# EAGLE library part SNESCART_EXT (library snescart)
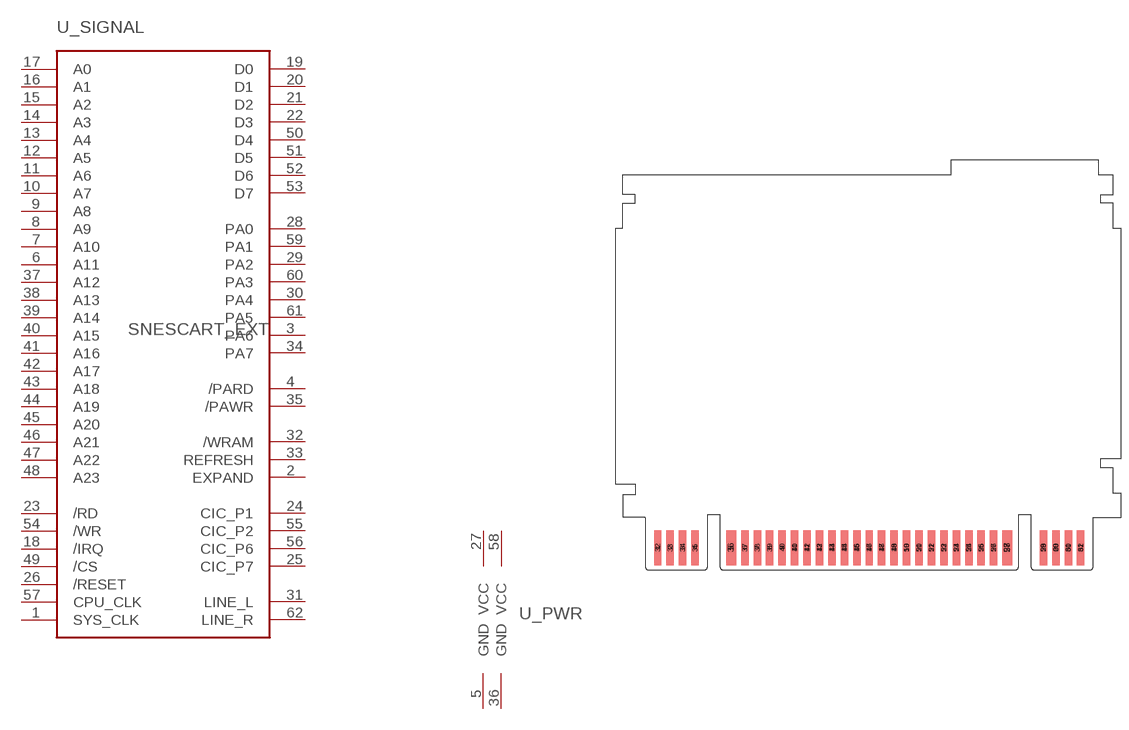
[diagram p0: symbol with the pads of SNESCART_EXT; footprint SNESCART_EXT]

Designator prefix -; gates _PWR=CART_PWR _SIGNAL=SNESCART_EXT

## SNESCART_EXTEDGE  [SNESCART_EXT]
1  _SIGNAL:SYS_CLK
2  _SIGNAL:EXPAND
3  _SIGNAL:PA6
4  _SIGNAL:/PARD
5  _PWR:GND  pwr
6  _SIGNAL:A11
7  _SIGNAL:A10
8  _SIGNAL:A9
9  _SIGNAL:A8
10  _SIGNAL:A7
11  _SIGNAL:A6
12  _SIGNAL:A5
13  _SIGNAL:A4
14  _SIGNAL:A3
15  _SIGNAL:A2
16  _SIGNAL:A1
17  _SIGNAL:A0
18  _SIGNAL:/IRQ
19  _SIGNAL:D0
20  _SIGNAL:D1
21  _SIGNAL:D2
22  _SIGNAL:D3
23  _SIGNAL:/RD
24  _SIGNAL:CIC_P1
25  _SIGNAL:CIC_P7
26  _SIGNAL:/RESET
27  _PWR:VCC  pwr
28  _SIGNAL:PA0
29  _SIGNAL:PA2
30  _SIGNAL:PA4
31  _SIGNAL:LINE_L
32  _SIGNAL:/WRAM
33  _SIGNAL:REFRESH
34  _SIGNAL:PA7
35  _SIGNAL:/PAWR
36  _PWR:GND  pwr
37  _SIGNAL:A12
38  _SIGNAL:A13
39  _SIGNAL:A14
40  _SIGNAL:A15
41  _SIGNAL:A16
42  _SIGNAL:A17
43  _SIGNAL:A18
44  _SIGNAL:A19
45  _SIGNAL:A20
46  _SIGNAL:A21
47  _SIGNAL:A22
48  _SIGNAL:A23
49  _SIGNAL:/CS
50  _SIGNAL:D4
51  _SIGNAL:D5
52  _SIGNAL:D6
53  _SIGNAL:D7
54  _SIGNAL:/WR
55  _SIGNAL:CIC_P2
56  _SIGNAL:CIC_P6
57  _SIGNAL:CPU_CLK
58  _PWR:VCC  pwr
59  _SIGNAL:PA1
60  _SIGNAL:PA3
61  _SIGNAL:PA5
62  _SIGNAL:LINE_R

## Footprint SNESCART_EXT (pad centres in mm)
smd 1.5 x 7: 1 -42.5,-0.5; 2 -40,-0.5; 3 -37.5,-0.5; 4 -35,-0.5; 6 -25,-0.5; 7 -22.5,-0.5; 8 -20,-0.5; 9 -17.5,-0.5; 10 -15,-0.5; 11 -12.5,-0.5; 12 -10,-0.5; 13 -7.5,-0.5; 14 -5,-0.5; 15 -2.5,-0.5; 16 0,-0.5; 17 2.5,-0.5; 18 5,-0.5; 19 7.5,-0.5; 20 10,-0.5; 21 12.5,-0.5; 22 15,-0.5; 23 17.5,-0.5; 24 20,-0.5; 25 22.5,-0.5; 26 25,-0.5; 28 35,-0.5; 29 37.5,-0.5; 30 40,-0.5; 31 42.5,-0.5
smd 2 x 7: 5 -27.75,-0.5; 27 27.75,-0.5
smd 1.5 x 7 bottom: 32 -42.5,-0.5; 33 -40,-0.5; 34 -37.5,-0.5; 35 -35,-0.5; 37 -25,-0.5; 38 -22.5,-0.5; 39 -20,-0.5; 40 -17.5,-0.5; 41 -15,-0.5; 42 -12.5,-0.5; 43 -10,-0.5; 44 -7.5,-0.5; 45 -5,-0.5; 46 -2.5,-0.5; 47 0,-0.5; 48 2.5,-0.5; 49 5,-0.5; 50 7.5,-0.5; 51 10,-0.5; 52 12.5,-0.5; 53 15,-0.5; 54 17.5,-0.5; 55 20,-0.5; 56 22.5,-0.5; 57 25,-0.5; 59 35,-0.5; 60 37.5,-0.5; 61 40,-0.5; 62 42.5,-0.5
smd 2 x 7 bottom: 36 -27.75,-0.5; 58 27.75,-0.5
